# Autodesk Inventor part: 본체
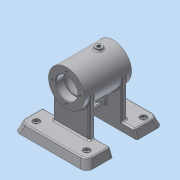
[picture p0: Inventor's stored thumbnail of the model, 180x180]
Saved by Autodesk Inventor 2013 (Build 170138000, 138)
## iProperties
Created: 2016-07
Part Number: 본체
Material: 알루미늄 6061
Document SubType Name: Modeling
Designer: Administrator
Density: 2.71 g/cm^3
Mass: 542.117 g
Surface Area: 571.142 cm^2
Volume: 200.043 cm^3
Author: Administrator
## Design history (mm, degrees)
sketch "스케치2"
  geometry: L1 (0, 0)-(70, 0); L2 (0, 0)-(0, 27); L3 (0, 27)-(70, 27); L4 (70, 0)-(70, 27); L5 (70, 16)-(58.3, 16); L6 (58, 15.7)-(58, 14); L7 (58, 14)-(56, 14); L8 (56, 14)-(56, 19); L9 (53, 22)-(17, 22); L10 (14, 19)-(14, 14); L11 (14, 14)-(12, 14); L12 (12, 14)-(12, 15.7); L13 (11.7, 16)-(0, 16); A1 r 3 centre (17, 19) between (17, 22) and (14, 19); A2 r 3 centre (53, 19) between (56, 19) and (53, 22); A3 r 0.3 centre (11.7, 15.7) between (12, 15.7) and (11.7, 16); A4 r 0.3 centre (58.3, 15.7) between (58.3, 16) and (58, 15.7)
  constraints: 26 end point, 8 point on circle, 8 tangent, 6 perpendicular, 5 parallel, 4 centre point, 2 equal radius, 2 point on line, 1 horizontal, 1 vertical
  dimensions: "d2" = 70 distance of L1.start L1.end; "d3" = 54 diameter of L3 L1; "d4" = 12 distance between parallel lines of L4 L6; "d5" = 32 diameter of L5 L1; "d6" = 28 diameter of L7 L1; "d7" = 2 distance between parallel lines of L6 L8; "d8" = 44 diameter of L9 L1; "d9" = 42 distance between parallel lines of L8 L10; "d10" = 32 diameter of L13 L1; "d11" = 28 diameter of L11 L1; "d12" = 12 distance between parallel lines of L2 L12; "d13" = 3 radius of A1; "d14" = 0.3 radius of A3
revolve "회전1" sketch "스케치2" stored, may be unused: angle "d15" = 90 deg
chamfer "모따기1" distance "d16" = 1; stored, may be unused: second distance "d17" = 2, angle "d18" = 45 deg
sketch "스케치3" dims "d19" = 42
  geometry: L1 (0, 0)-(0, 21); C1 r 17 at (0, 0) reference; C2 r 2 at (0, 21)
  constraints: 2 coincident, 2 end point, 1 centre point, 1 vertical, 1 vertical alignment, 2 other
  dimensions: "d21" = 4 diameter of C2
hole "구멍1" sketch "스케치3" at (0, 21) diameter "d22" = 3.242; stored, may be unused: countersink angle "d26" = 90 deg, drill point angle "d28" = 118 deg; dims "d23" = 8, "d24" = 4, "d25" = 2, "d27" = 10
node "작업 평면1"
node "작업 평면2"
sketch "스케치4"
  geometry: L1 (27, 70)-(-27, 70) reference; L2 (-50, 90)-(50, 90); L3 (50, 90)-(50, 55); L4 (50, 55)-(-50, 55); L5 (-50, 55)-(-50, 90); L6 (-27, 0)-(-27, 70) reference; L7 (27, 0)-(27, 70) reference; L8 (-27, 35)-(27, 35); 1 further point
  constraints: 10 end point, 2 midpoint, 2 parallel, 1 horizontal, 1 perpendicular
  dimensions: "d33" = 100 distance between parallel lines of L3 L5; "d35" = 50 distance from line of point (0, 0) L5; "d36" = 35 distance between parallel lines of L4 L2; "d37" = 55 distance between parallel lines of L8 L2
extrude "돌출1" join sketch "스케치4" distance "d38" = 12; taper "d39" = 0 deg
node "작업 평면3"
node "작업 평면4"
sketch "스케치6"
  geometry: L1 (0, 27)-(0, -27); L2 (0, 0)-(15.898, -25.441); A1 r 27 centre (0, 0) between (0, 27) and (0, -27) reference; 1 further point
  constraints: 4 end point, 2 point on circle, 1 midpoint, 1 vertical
  dimensions: "d48" = 30 distance of L2.start L2.end; "d49" = 32 deg angle of L2 L1
node "작업 평면5"
sketch "스케치7"
  geometry: C1 r 6 at (0, 0); 2 further points
  constraints: 1 centre point, 1 coincident
  dimensions: "d50" = 12 diameter of C1
extrude "돌출3" join sketch "스케치7" stored distance "d52" = 12; taper "d53" = 0 deg
fillet "모깎기1" dims "d54" = 2
sketch "스케치9"
  geometry: C1 r 6 at (0, 0) reference; 1 further point
hole "구멍3" sketch "스케치9" at (0, 0) diameter "d62" = 5.188; stored, may be unused: countersink angle "d66" = 90 deg, drill point angle "d68" = 118 deg; dims "d63" = 8, "d64" = 10, "d65" = 4, "d67" = 10
sketch "스케치10" dims "d108" = 2
  geometry: L1 (100, 0)-(0, 0) reference; L2 (0, 0)-(0, 35) reference; C1 r 5 at (12.5, 12.5); C2 r 5 at (87.5, 12.5); 1 further point
  constraints: 2 centre point, 1 equal radius
  dimensions: "d69" = 10 diameter of C1; "d71" = 12.5 distance from line of L1 C1.centre; "d72" = 12.5 distance from line of C1.centre L2; "d73" = 75 distance of C2.centre C1.centre; "d74" = 12.5 distance from line of L1 C2.centre
hole "구멍4" sketch "스케치10" at (12.5, 12.5), (87.5, 12.5) diameter "d75" = 6; stored, may be unused: countersink angle "d79" = 90 deg, drill point angle "d81" = 118 deg; dims "d76" = 8, "d77" = 10, "d78" = 4, "d80" = 10
feature "면 기울기1" dims angle "d82" = 20 deg
feature "면 기울기2" dims angle "d84" = 20 deg
sketch "스케치11"
  geometry: L1 (0, 35)-(100, 35) reference; L2 (23, 35)-(77, 35); L3 (77, 35)-(77, 27); L4 (77, 27)-(23, 27); L5 (23, 27)-(23, 35); 1 further point
  constraints: 8 end point, 2 parallel, 1 horizontal, 1 perpendicular, 1 point on line
  dimensions: "d85" = 8 distance between parallel lines of L4 L1; "d86" = 54 distance between parallel lines of L3 L5; "d87" = 27 distance from line of point (50, 20) L5
extrude "돌출4" join sketch "스케치11" stored distance "d88" = 12; taper "d89" = 0 deg
node "작업 평면6"
sketch "스케치12"
  geometry: L1 (-31, -7)-(-31, 63) reference; L2 (0, 8)-(-58, 8) reference; L3 (0, 48)-(-58, 48) reference; L4 (-10, 8)-(-10, 48); 1 further point
  constraints: 2 end point, 2 point on line, 1 perpendicular
  dimensions: "d90" = 21 distance between parallel lines of L4 L1
feature "리브1" sketch "스케치12" dims "d91" = 1, "d92" = 8, "d93" = 0, "d94" = 0, "d95" = 1, "d96" = 1
sketch "스케치13"
  geometry: L1 (21.298, 40)-(21.298, 0) reference; L2 (7.798, 28)-(7.798, 12); L3 (14.798, 12)-(14.798, 28); L4 (-53.702, -15)-(-53.702, 55) reference; L5 (-53.702, 20)-(21.298, 20); L6 (43.298, 79.368)-(43.298, 40) reference; A1 r 3.5 centre (11.298, 12) between (7.798, 12) and (14.798, 12); A2 r 3.5 centre (11.298, 28) between (14.798, 28) and (7.798, 28); 1 further point
  constraints: 6 end point, 6 point on circle, 4 tangent, 2 centre point, 2 midpoint, 2 point on line, 1 equal radius, 1 vertical
  dimensions: "d99" = 23 dimension on A2 A1; "d101" = 8 vertical distance of L5.end A1.centre; "d102" = 3.5 radius of A1; "d103" = 32 distance from line of L6 A2.centre
extrude "돌출5" cut sketch "스케치13" stored distance "d104" = 12; taper "d105" = 0 deg
fillet "모깎기3" dims "d106" = 2
fillet "모깎기4" dims "d107" = 10
fillet "모깎기5" dims "d108" = 2
fillet "모깎기6" dims "d109" = 2
fillet "모깎기7" dims "d110" = 2
fillet "모깎기8" dims "d111" = 2
node "작업 평면7"
sketch "스케치14"
  geometry: L1 (27, 70)-(-27, 70) reference; C1 r 5 at (0, 48); 1 further point
  constraints: 1 centre point
  dimensions: "d113" = 0 horizontal distance of point (0, 0) C1.centre; "d114" = 10 diameter of C1; "d115" = 22 distance from line of C1.centre L1
extrude "돌출6" join sketch "스케치14" stored distance "d116" = 12; taper "d117" = 0 deg
sketch "스케치15"
  geometry: C1 r 5 at (0, 0) reference; 1 further point
hole "구멍5" sketch "스케치15" at (0, 0) diameter "d118" = 5.188; stored, may be unused: countersink angle "d122" = 90 deg, drill point angle "d124" = 118 deg; dims "d119" = 8, "d120" = 10, "d121" = 4, "d123" = 10
fillet "모깎기9" dims "d125" = 2
fillet "모깎기10" dims "d126" = 2
node "작업 평면8"
sketch "스케치16"
  geometry: L1 (-55.739, 3.002)-(-14.261, 3.002); L2 (-14.261, 3.002)-(-14.261, -3.002); L3 (-14.261, -3.002)-(-55.739, -3.002); L4 (-55.739, -3.002)-(-55.739, 3.002); L5 (-55.739, 0)-(-14.261, 0); L6 (-35, 3.002)-(-35, -3.002); L7 (-70, 27)-(-70, -27) reference; 1 further point
  constraints: 4 end point, 4 midpoint, 2 other
  dimensions: "d129" = 35 distance between parallel lines of L6 L7; "d130" = 0 distance from line of point (0, 0) L5
feature "엠보싱1" sketch "스케치16" dims "d2" = 70, "d3" = 54, "d4" = 12, "d5" = 32, "d6" = 28, "d7" = 2, "d8" = 44, "d9" = 42, "d10" = 32, "d11" = 28, "d12" = 12, "d13" = 3, "d14" = 0.3, "d131" = 0.5, "d132" = 0
fillet "모깎기11" dims "d133" = 2
node "솔리드1"
pattern_circular "원형 패턴1" dims angle "d30" = 360 deg
mirror "대칭1"
mirror "대칭2"
mirror "대칭3"
mirror "대칭4"
